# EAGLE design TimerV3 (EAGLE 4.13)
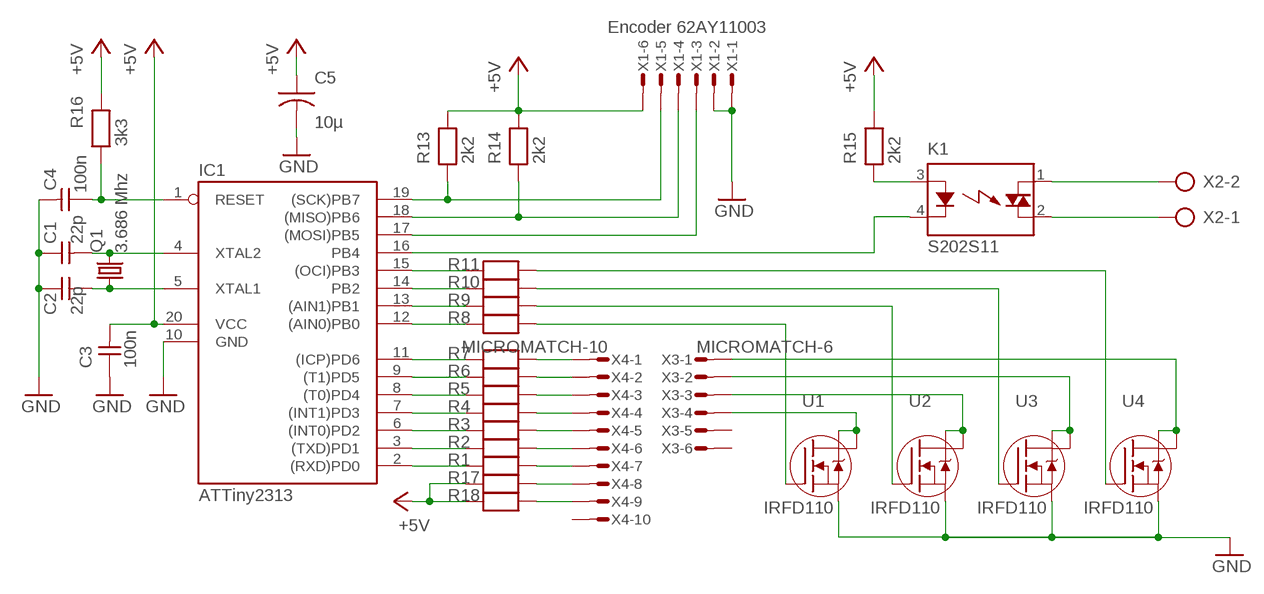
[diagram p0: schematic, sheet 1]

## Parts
C1  22p  CAPNP-2,5  [C-2,5]
C2  22p  CAPNP-2,5  [C-2,5]
C3  100n  CAPNP-2,5  [C-2,5]
C4  100n  CAPNP-2,5  [C-2,5]
C5  10µ  CAP-2,5  [C-2,5]
IC1  ATTiny2313  AT90S2313P  [DIL20]
K1  S202S11  S202T02  [S102T0X]
Q1  3.686 Mhz  CRYTALHC49S  [HC49/S]
R1  RESEU-7,5  [R-7,5]
R2  RESEU-7,5  [R-7,5]
R3  RESEU-7,5  [R-7,5]
R4  RESEU-7,5  [R-7,5]
R5  RESEU-7,5  [R-7,5]
R6  RESEU-7,5  [R-7,5]
R7  RESEU-7,5  [R-7,5]
R8  RESEU-7,5  [R-7,5]
R9  RESEU-7,5  [R-7,5]
R10  RESEU-7,5  [R-7,5]
R11  RESEU-7,5  [R-7,5]
R13  2k2  RESEU-7,5  [R-7,5]
R14  2k2  RESEU-7,5  [R-7,5]
R15  2k2  RESEU-7,5  [R-7,5]
R16  3k3  RESEU-7,5  [R-7,5]
R17  RESEU-7,5  [R-7,5]
R18  RESEU-7,5  [R-7,5]
U1  IRFD110  [DIL04]
U2  IRFD110  [DIL04]
U3  IRFD110  [DIL04]
U4  IRFD110  [DIL04]
X1  Encoder 62AY11003  MICROMATCH-6  [MICROMATCH-6]
X2  AK500/2  [AK500/2]
X3  MICROMATCH-6  [MICROMATCH-6]
X4  MICROMATCH-10  [MICROMATCH-10]

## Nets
+5V: C3.2 C5.1 IC1.20(VCC) R13.2 R14.2 R15.2 R16.2 R17.1 R18.1 X1.6
GND: C1.1 C2.1 C3.1 C4.2 C5.2 IC1.10(GND) U1.4(S) U2.4(S) U3.4(S) U4.4(S) X1.1 X1.2
N$1: IC1.16(PB4) K1.4(K)
N$2: IC1.15((OCI)PB3) R11.1
N$3: IC1.14(PB2) R10.1
N$4: IC1.13((AIN1)PB1) R9.1
N$5: IC1.12((AIN0)PB0) R8.1
N$6: IC1.11((ICP)PD6) R7.1
N$7: IC1.9((T1)PD5) R6.1
N$8: IC1.8((T0)PD4) R5.1
N$9: IC1.7((INT1)PD3) R4.1
N$10: IC1.6((INT0)PD2) R3.1
N$11: IC1.3((TXD)PD1) R2.1
N$12: IC1.2((RXD)PD0) R1.1
N$13: C1.2 IC1.4(XTAL2) Q1.2
N$14: C2.2 IC1.5(XTAL1) Q1.1
N$15: IC1.19((SCK)PB7) R13.1 X1.5
N$16: IC1.17((MOSI)PB5) X1.3
N$17: R8.2 U1.3(G)
N$18: R9.2 U2.3(G)
N$19: R10.2 U3.3(G)
N$20: IC1.18((MISO)PB6) R14.1 X1.4
N$21: R11.2 U4.3(G)
N$22: K1.3(A) R15.1
N$24: U1.1(D) U1.2(D) X3.4
N$25: U2.1(D) U2.2(D) X3.3
N$26: U3.1(D) U3.2(D) X3.2
N$27: U4.1(D) U4.2(D) X3.1
N$28: K1.1(DS1) X2.2
N$29: K1.2(DS2) X2.1
N$30: C4.1 IC1.1(RESET) R16.1
N$35: R7.2 X4.1
N$36: R6.2 X4.2
N$37: R5.2 X4.3
N$38: R4.2 X4.4
N$39: R3.2 X4.5
N$40: R2.2 X4.6
N$41: R1.2 X4.7
N$42: R17.2 X4.8
N$43: R18.2 X4.9
Unconnected: X3.5 X3.6 X4.10

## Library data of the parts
C1-C4 = discrete:CAPNP-2,5
C5 = discrete:CAP-2,5
IC1 = atmel2:AT90S2313: MICROCONTROLLER 2 Kbytes FLASH 128 bytes SRAM 128 bytes EEPROM UART
K1 = relay:S?02T*: Low Height Type Solid State Relays SHARP Source: 162574-da-01-en-S202T02_Solid_State_Relais.pdf
Q1 = crystal:CRYTAL: CRYSTAL
R1-R11 R13-R18 = discrete:RESEU-7,5
U1-U4 = irf-2:IRFD110
X1 X3 = con-amp-micromatch:MICROMATCH-6: MicroMaTch 6 7-215464-6 / 0-215464-6 Drawing Number C-215464 DDEController.pdf
X2 = con-ptr500:AK500/2: CONNECTOR
X4 = con-amp-micromatch:MICROMATCH-10: MicroMaTch 10 8-215464-0 / 1-215464-0 Drawing Number C-215464 DDEController.pdf

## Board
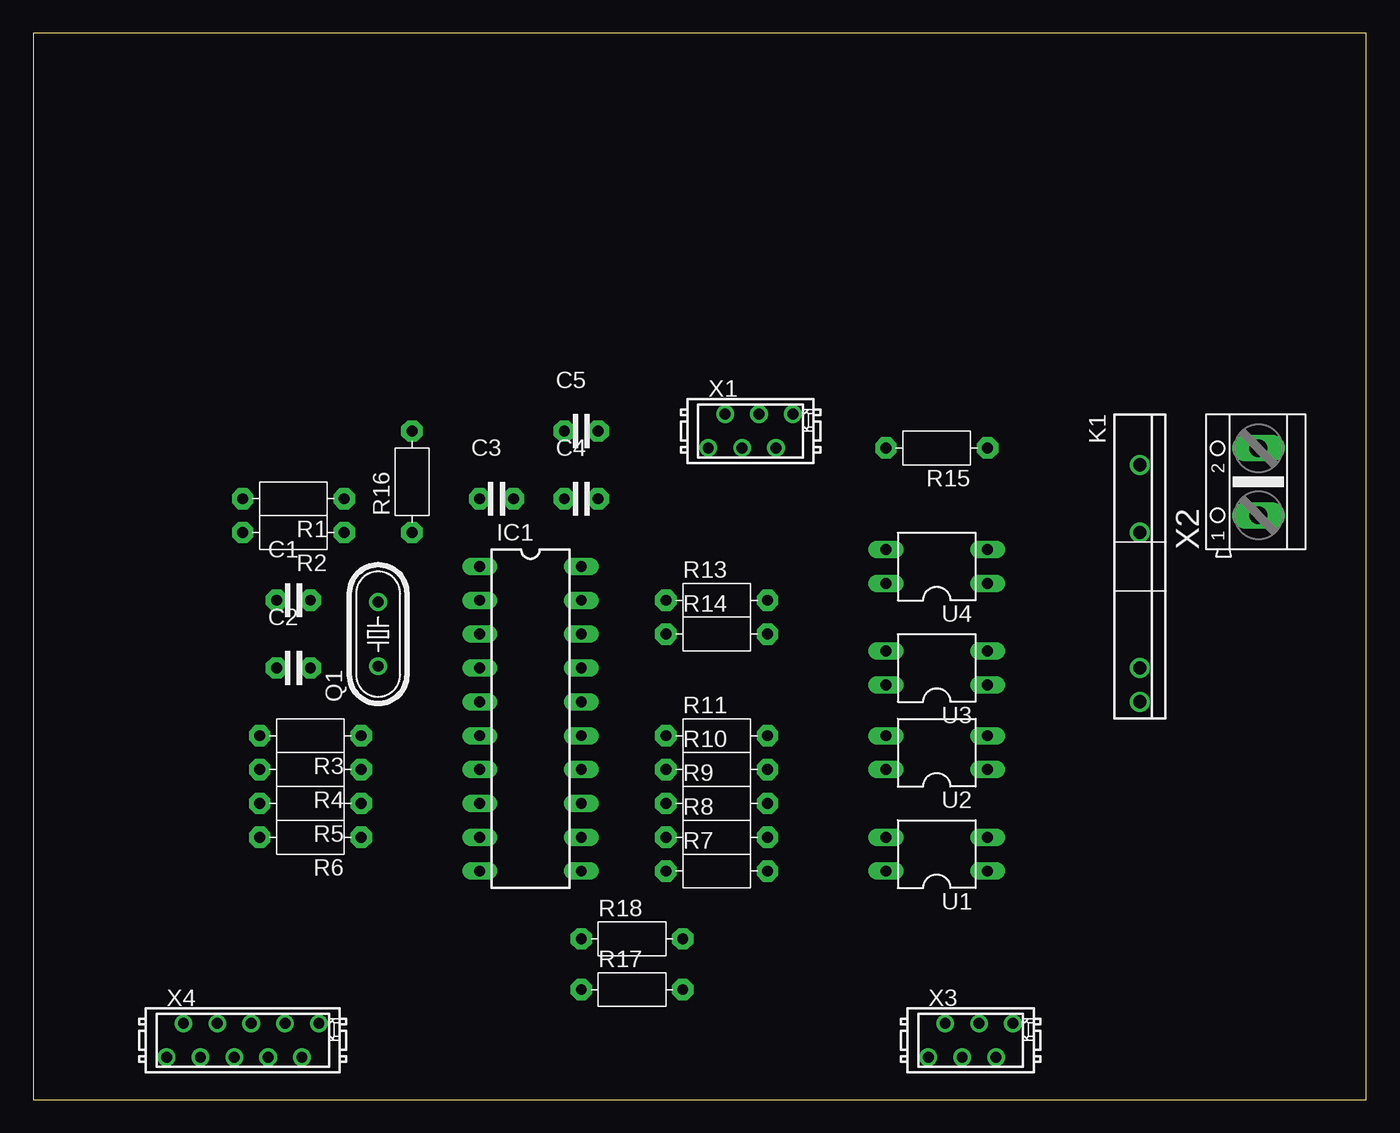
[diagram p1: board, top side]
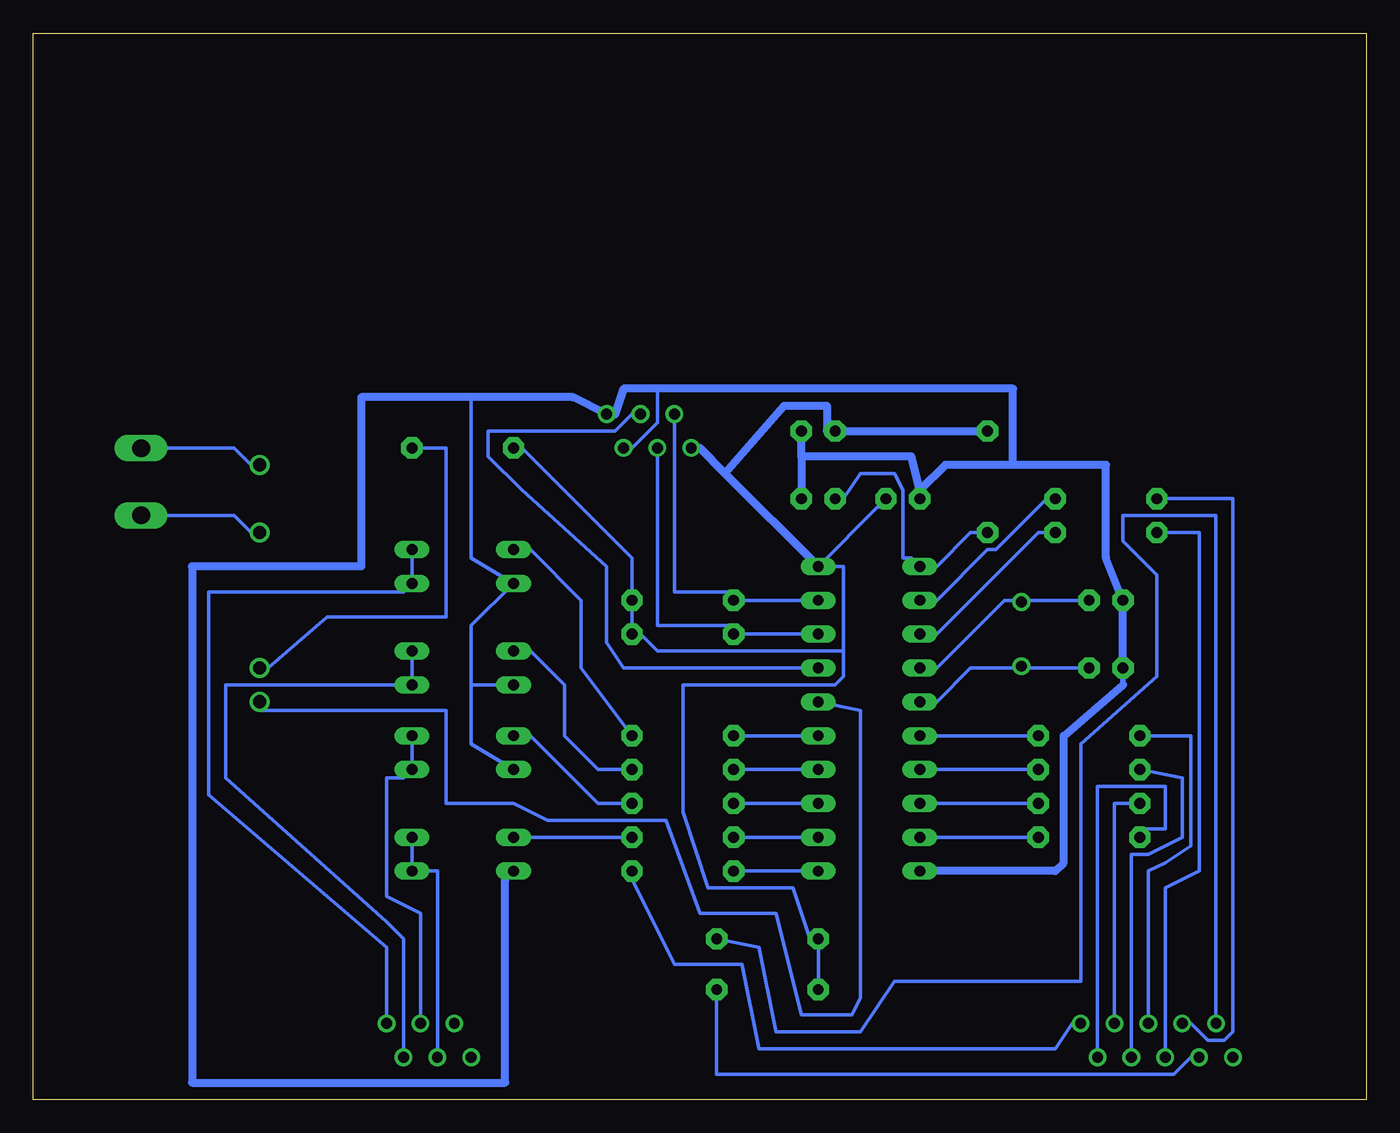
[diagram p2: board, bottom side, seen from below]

Size 100 x 80 mm. Coordinates in mm from the lower left corner, seen from the top.
Outline: 0,0 100,0 100,80 0,80 0,0
Copper layers (1*16): Top 0.035mm / dielectric 1.5mm / Bottom 0.035mm
Design rules "default": minimum track width 10mil, minimum drill 24mil, track to track 8mil, track to pad 8mil, pad to pad 8mil, via to via 8mil, smd to smd 8mil, copper to edge 40mil, drill to drill 8mil, minimum pad ring 10mil, minimum via ring 8mil, stop-mask expansion 4mil, vias tented up to drill 0mil, thermal gap 10mil

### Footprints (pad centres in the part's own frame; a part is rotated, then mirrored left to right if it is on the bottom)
C-2,5 = drill 0.813 pad 1.6 octagon: 1 -1.27,0; 2 1.27,0
DIL20 = drill 0.813 long: 1 -11.43,-3.81; 2 -8.89,-3.81; 3 -6.35,-3.81; 4 -3.81,-3.81; 5 -1.27,-3.81; 6 1.27,-3.81; 7 3.81,-3.81; 8 6.35,-3.81; 9 8.89,-3.81; 10 11.43,-3.81; 11 11.43,3.81; 12 8.89,3.81; 13 6.35,3.81; 14 3.81,3.81; 15 1.27,3.81; 16 -1.27,3.81; 17 -3.81,3.81; 18 -6.35,3.81; 19 -8.89,3.81; 20 -11.43,3.81
S102T0X = drill 1 round: 1 -7.62,0; 2 -2.54,0; 3 7.62,0; 4 10.16,0
HC49/S = drill 0.813 round: 1 -2.413,0; 2 2.413,0
R-7,5 = drill 0.813 pad 1.6 octagon: 1 -3.81,0; 2 3.81,0
DIL04 = drill 0.813 long: 1 -1.27,-3.81; 2 1.27,-3.81; 3 1.27,3.81; 4 -1.27,3.81
MICROMATCH-6 = drill 0.813 round: 1 3.175,1.27; 2 1.905,-1.27; 3 0.635,1.27; 4 -0.635,-1.27; 5 -1.905,1.27; 6 -3.175,-1.27
AK500/2 = drill 1.321 long: 1 -2.515,0; 2 2.515,0
MICROMATCH-10 = drill 0.813 round: 1 5.715,1.27; 2 4.445,-1.27; 3 3.175,1.27; 4 1.905,-1.27; 5 0.635,1.27; 6 -0.635,-1.27; 7 -1.905,1.27; 8 -3.175,-1.27; 9 -4.445,1.27; 10 -5.715,-1.27

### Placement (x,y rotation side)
C1  19.52,37.46 0 top
C2  19.52,32.38 0 top
C3  34.76,45.08 0 top
C4  41.11,45.08 0 top
C5  41.11,50.16 0 top
IC1  37.3,28.57 270 top
K1  83.02,40 270 top
Q1  25.87,34.92 90 top
R1  19.52,45.08 180 top
R2  19.52,42.54 180 top
R3  20.79,27.3 180 top
R4  20.79,24.76 180 top
R5  20.79,22.22 180 top
R6  20.79,19.68 180 top
R7  51.27,17.14 0 top
R8  51.27,19.68 0 top
R9  51.27,22.22 0 top
R10  51.27,24.76 0 top
R11  51.27,27.3 0 top
R13  51.27,37.46 0 top
R14  51.27,34.92 0 top
R15  67.78,48.89 180 top
R16  28.41,46.35 90 top
R17  44.92,8.25 0 top
R18  44.92,12.06 0 top
U1  67.78,18.41 90 top
U2  67.78,26.03 90 top
U3  67.78,32.38 90 top
U4  67.78,40 90 top
X1  53.81,50.16 0 top
X2  91.91,46.35 90 top
X3  70.32,4.44 0 top
X4  15.71,4.44 0 top

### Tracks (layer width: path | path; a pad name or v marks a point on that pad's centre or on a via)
+5V
  Bottom 0.254: R15.2 63.34,48.89 55.08,40.64 R13.2 R14.2 54.45,34.92 53.17,33.65 39.2,33.65 | R17.1 R18.1 41.74,12.06 43.02,15.87 49.37,15.87 51.27,21.58 51.27,31.11 39.84,31.11 39.2,31.74 39.2,33.65 | C3.2 36.03,44.45 36.66,44.45 IC1.20 39.2,40 39.2,33.65 | 50,48.89 X1.6 | 40.48,50.16 C5.1
  Bottom 0.61: C5.1 R16.2 | 48.09,46.98 50,48.89 | IC1.20 48.09,46.98 | 40.48,50.16 40.48,52.07 43.65,52.07 48.09,46.98
GND
  Bottom 0.254: C2.1 18.88,32.38 | 31.58,47.62 34.12,45.08 C3.1 33.49,45.72 | 67.14,31.11 67.14,26.66 U2.4 | 67.14,31.11 67.14,35.55 U4.4 67.14,40.64 67.14,52.7 | 67.14,31.11 U3.4 | 53.17,53.34 53.17,50.8 55.08,48.89 X1.2 | 56.35,51.43 X1.1 | 64.61,16.5 U1.4
  Bottom 0.406: 18.25,31.11 C2.1 | IC1.10 32.22,17.14
  Bottom 0.61: 42.38,48.26 34.12,48.26 33.49,45.72 31.58,47.62 26.5,47.62 | 42.38,48.26 C4.2 | 42.38,48.26 C5.2 | C2.1 C1.1 19.52,40.64 19.52,47.62 26.5,47.62 | 56.35,51.43 55.71,53.34 53.17,53.34 26.5,53.34 26.5,47.62 | 64.61,16.5 64.61,1.27 88.1,1.27 88.1,40 75.4,40 75.4,52.7 67.14,52.7 59.52,52.7 X1.1 | 18.25,31.11 22.7,27.3 22.7,17.77 23.33,17.14 IC1.10
N$1
  Bottom 0.254: IC1.16 37.94,29.2 37.94,7.62 38.57,6.34 42.38,6.34 44.28,13.97 50,13.97 52.54,20.95 61.43,20.95 63.97,22.22 69.05,22.22 69.05,29.2 83.02,29.2 K1.4
N$2
  Bottom 0.254: IC1.15 R11.1
N$3
  Bottom 0.254: IC1.14 R10.1
N$4
  Bottom 0.254: IC1.13 R9.1
N$5
  Bottom 0.254: IC1.12 R8.1
N$6
  Bottom 0.254: IC1.11 R7.1
N$7
  Bottom 0.254: R6.1 IC1.9
N$8
  Bottom 0.254: R5.1 IC1.8
N$9
  Bottom 0.254: R4.1 IC1.7
N$10
  Bottom 0.254: R3.1 IC1.6
N$11
  Bottom 0.254: IC1.3 32.22,34.92 24.6,42.54 R2.1
N$12
  Bottom 0.254: IC1.2 32.22,37.46 28.41,41.27 27.77,41.27 23.96,45.08 R1.1
N$13
  Bottom 0.254: IC1.4 32.22,32.38 27.14,37.46 26.5,37.46 Q1.2 25.23,37.46 C1.2
N$14
  Bottom 0.254: IC1.5 32.22,29.84 29.68,32.38 26.5,32.38 Q1.1 25.23,32.38 C2.2
N$15
  Bottom 0.254: IC1.19 R13.1 47.46,38.1 51.91,38.1 X1.5
N$16
  Bottom 0.254: IC1.17 55.71,32.38 56.98,34.29 56.98,40 63.34,45.72 65.88,48.26 65.88,50.16 56.35,50.16 55.08,51.43 X1.3
N$17
  Bottom 0.254: R8.2 U1.3
N$18
  Bottom 0.254: U2.3 62.7,27.3 57.62,22.22 R9.2
N$19
  Bottom 0.254: U3.3 62.7,33.65 60.16,31.11 60.16,27.3 57.62,24.76 R10.2
N$20
  Bottom 0.254: IC1.18 R14.1 47.46,35.55 53.17,35.55 X1.4
N$21
  Bottom 0.254: R11.2 58.89,32.38 58.89,37.46 62.7,41.27 U4.3
N$22
  Bottom 0.254: K1.3 82.39,32.38 77.94,36.19 69.05,36.19 69.05,48.89 R15.1
N$24
  Bottom 0.254: X3.4 69.69,17.14 U1.1 U1.2
N$25
  Bottom 0.254: X3.3 70.95,13.97 73.5,15.24 73.5,24.12 72.22,24.12 U2.1 U2.2
N$26
  Bottom 0.254: X3.2 72.22,12.06 73.5,13.33 85.56,24.12 85.56,31.11 U3.1 U3.2
N$27
  Bottom 0.254: X3.1 73.5,11.43 86.83,22.86 86.83,38.1 72.22,38.1 U4.1 U4.2
N$28
  Bottom 0.254: K1.1 83.66,47.62 84.92,48.89 90,48.89 X2.2
N$29
  Bottom 0.254: K1.2 83.66,42.54 84.92,43.81 90,43.81 X2.1
N$30
  Bottom 0.254: R16.1 29.68,42.54 32.22,40 IC1.1 34.12,40.64 34.76,40.64 34.76,45.72 35.39,46.98 37.94,46.98 39.2,45.08 C4.1
N$35
  Bottom 0.254: X4.1 22.06,5.71 23.33,3.8 45.55,3.8 46.82,10.16 51.91,10.16 55.08,16.5 R7.2
N$36
  Bottom 0.254: X4.2 20.15,23.49 15.08,23.49 15.08,20.31 16.98,20.31 R6.2
N$37
  Bottom 0.254: R5.2 18.88,22.22 X4.3
N$38
  Bottom 0.254: X4.4 17.61,18.41 16.34,18.41 13.81,19.68 13.81,24.12 R4.2
N$39
  Bottom 0.254: X4.5 16.34,17.14 15.08,17.77 13.17,19.04 13.17,27.3 R3.2
N$40
  Bottom 0.254: X4.6 15.08,15.87 12.54,17.14 12.54,42.54 R2.2
N$41
  Bottom 0.254: X4.7 13.17,5.71 11.9,4.44 10.63,4.44 10,5.08 10,45.08 R1.2
N$42
  Bottom 0.254: X4.8 13.17,3.17 14.44,1.9 48.73,1.9 R17.2
N$43
  Bottom 0.254: X4.9 11.27,43.81 18.25,43.81 18.25,41.91 15.71,39.37 15.71,31.74 21.42,26.66 21.42,8.89 35.39,8.89 37.94,5.08 44.28,5.08 45.55,11.43 R18.2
